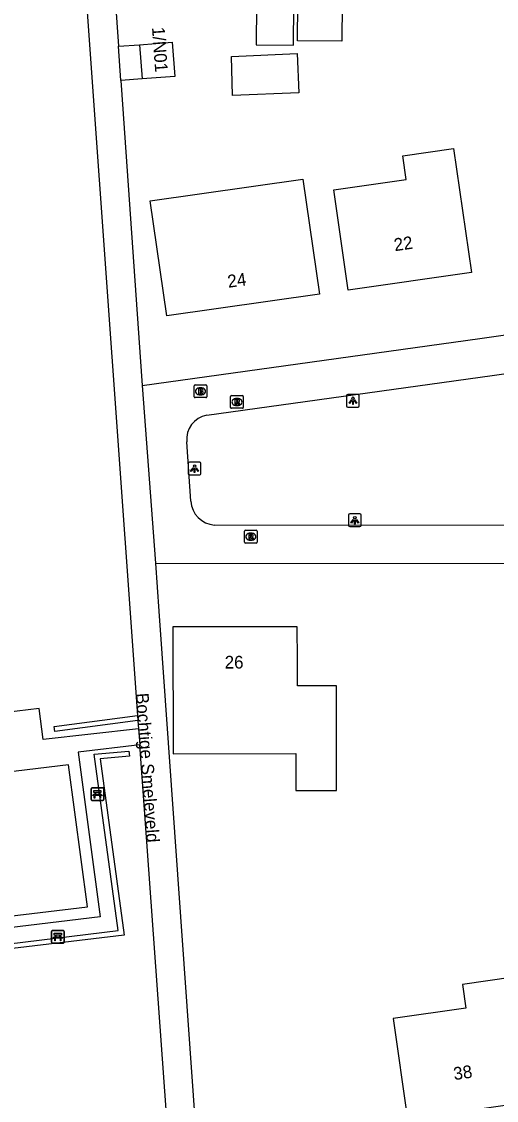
# Model space of a CAD drawing. Extents: x 162675 to 163482, y 379761 to 381227.
# Drawn here: x 162956.1 to 162993.6, y 380587.3 to 380672.3 of the extents above; entities that cross this region are included whole.
import ezdxf

# ---------------------------------------------------------------- set-up
doc = ezdxf.new("R2010")
doc.units = 0
for name, color, linetype in [('IMGEO_Bank', 7, 'Continuous'), ('IMGEO_Brandkraan', 7, 'Continuous'), ('IMGEO_Haag', 7, 'Continuous'), ('IMGEO_Lichtpunt', 7, 'Continuous'), ('IMGEO_Openbare_ruimte_label', 7, 'Continuous'), ('IMGEO_Pand', 7, 'Continuous'), ('IMGEO_Pand_nummerreeks', 7, 'Continuous'), ('IMGEO_Rijbaan_lokaal_open', 7, 'Continuous'), ('IMGEO_Rioolput', 7, 'Continuous'), ('IMGEO_Voetpad_open', 7, 'Continuous')]:
    doc.layers.add(name, color=color, linetype=linetype)

msp = doc.modelspace()

# ---------------------------------------------------------------- linework, layer by layer
at = {"layer": 'IMGEO_Bank'}
for p, q in [((162961.628, 380610.973), (162961.628, 380611.814)), ((162961.628, 380611.814), (162961.628, 380610.973)), ((162961.703, 380611.898), (162962.544, 380611.898)), ((162962.544, 380611.898), (162961.703, 380611.898)), ((162962.628, 380611.823), (162962.628, 380610.982)), ((162962.628, 380610.982), (162962.628, 380611.823)), ((162962.553, 380610.898), (162961.712, 380610.898)), ((162961.712, 380610.898), (162962.553, 380610.898)), ((162962.325, 380611.296), (162961.932, 380611.296)), ((162961.937, 380611.404), (162961.937, 380611.51)), ((162961.981, 380611.51), (162961.981, 380611.404)), ((162962.269, 380611.516), (162961.987, 380611.516)), ((162961.987, 380611.398), (162962.269, 380611.398)), ((162962.275, 380611.404), (162962.275, 380611.51)), ((162962.319, 380611.51), (162962.319, 380611.404)), ((162958.508, 380599.725), (162958.508, 380600.566)), ((162958.508, 380600.566), (162958.508, 380599.725)), ((162958.583, 380600.65), (162959.424, 380600.65)), ((162959.424, 380600.65), (162958.583, 380600.65)), ((162959.508, 380600.575), (162959.508, 380599.734)), ((162959.508, 380599.734), (162959.508, 380600.575)), ((162959.433, 380599.65), (162958.592, 380599.65)), ((162958.592, 380599.65), (162959.433, 380599.65)), ((162959.205, 380600.048), (162958.812, 380600.048)), ((162958.817, 380600.156), (162958.817, 380600.262)), ((162958.861, 380600.262), (162958.861, 380600.156)), ((162959.149, 380600.268), (162958.867, 380600.268)), ((162958.867, 380600.15), (162959.149, 380600.15)), ((162959.155, 380600.156), (162959.155, 380600.262)), ((162959.199, 380600.262), (162959.199, 380600.156))]:
    msp.add_line(p, q, dxfattribs=at)
for points in [[(162961.931, 380611.516), (162961.845, 380611.516), (162961.845, 380611.677), (162962.408, 380611.677), (162962.408, 380611.516), (162962.325, 380611.516)], [(162961.875, 380611.296), (162961.733, 380611.296), (162961.845, 380611.398), (162961.931, 380611.398)], [(162961.925, 380611.289), (162961.925, 380611.082), (162961.882, 380611.082), (162961.882, 380611.289)], [(162962.325, 380611.398), (162962.408, 380611.398), (162962.52, 380611.296), (162962.381, 380611.296)], [(162962.375, 380611.289), (162962.375, 380611.082), (162962.331, 380611.082), (162962.331, 380611.289)], [(162958.755, 380600.048), (162958.613, 380600.048), (162958.725, 380600.15), (162958.811, 380600.15)], [(162958.811, 380600.268), (162958.725, 380600.268), (162958.725, 380600.429), (162959.288, 380600.429), (162959.288, 380600.268), (162959.205, 380600.268)], [(162958.805, 380600.041), (162958.805, 380599.834), (162958.762, 380599.834), (162958.762, 380600.041)], [(162959.205, 380600.15), (162959.288, 380600.15), (162959.4, 380600.048), (162959.261, 380600.048)], [(162959.255, 380600.041), (162959.255, 380599.834), (162959.211, 380599.834), (162959.211, 380600.041)]]:
    msp.add_lwpolyline(points, dxfattribs=at)
for centre, radius, start, end in [((162961.706, 380611.82), 0.0779, 92.4484, 184.28452), ((162961.706, 380611.82), 0.0779, 92.4484, 184.28452), ((162962.55, 380611.82), 0.0779, 2.4484, 94.28452), ((162962.55, 380611.82), 0.0779, 2.4484, 94.28452), ((162961.706, 380610.976), 0.0779, 182.4484, 274.28452), ((162961.706, 380610.976), 0.0779, 182.4484, 274.28452), ((162961.875, 380611.289), 0.00671, 2.89567, 87.10433), ((162961.932, 380611.289), 0.00671, 92.89567, 177.10433), ((162961.93, 380611.509), 0.00671, 2.89567, 87.10433), ((162961.93, 380611.405), 0.00671, 272.89567, 357.10433), ((162961.987, 380611.509), 0.00671, 92.89567, 177.10433), ((162961.987, 380611.405), 0.00671, 182.89567, 267.10433), ((162962.269, 380611.509), 0.00671, 2.89567, 87.10433), ((162962.269, 380611.405), 0.00671, 272.89567, 357.10433), ((162962.326, 380611.509), 0.00671, 92.89567, 177.10433), ((162962.326, 380611.405), 0.00671, 182.89567, 267.10433), ((162962.324, 380611.289), 0.00671, 2.89567, 87.10433), ((162962.381, 380611.289), 0.00671, 92.89567, 177.10433), ((162962.55, 380610.976), 0.0779, 272.4484, 4.28452), ((162962.55, 380610.976), 0.0779, 272.4484, 4.28452), ((162958.586, 380600.572), 0.0779, 92.4484, 184.28452), ((162958.586, 380600.572), 0.0779, 92.4484, 184.28452), ((162959.43, 380600.572), 0.0779, 2.4484, 94.28452), ((162959.43, 380600.572), 0.0779, 2.4484, 94.28452), ((162958.586, 380599.728), 0.0779, 182.4484, 274.28452), ((162958.586, 380599.728), 0.0779, 182.4484, 274.28452), ((162958.755, 380600.041), 0.00671, 2.89567, 87.10433), ((162958.812, 380600.041), 0.00671, 92.89567, 177.10433), ((162958.81, 380600.261), 0.00671, 2.89567, 87.10433), ((162958.81, 380600.157), 0.00671, 272.89567, 357.10433), ((162958.867, 380600.261), 0.00671, 92.89567, 177.10433), ((162958.867, 380600.157), 0.00671, 182.89567, 267.10433), ((162959.149, 380600.261), 0.00671, 2.89567, 87.10433), ((162959.149, 380600.157), 0.00671, 272.89567, 357.10433), ((162959.206, 380600.261), 0.00671, 92.89567, 177.10433), ((162959.206, 380600.157), 0.00671, 182.89567, 267.10433), ((162959.204, 380600.041), 0.00671, 2.89567, 87.10433), ((162959.261, 380600.041), 0.00671, 92.89567, 177.10433), ((162959.43, 380599.728), 0.0779, 272.4484, 4.28452), ((162959.43, 380599.728), 0.0779, 272.4484, 4.28452)]:
    msp.add_arc(centre, radius, start, end, dxfattribs=at)
at = {"layer": 'IMGEO_Brandkraan'}
for p, q in [((162969.753, 380642.72), (162969.753, 380643.572)), ((162969.828, 380643.646), (162970.68, 380643.646)), ((162970.241, 380643.426), (162970.266, 380643.426)), ((162970.754, 380643.572), (162970.754, 380642.72)), ((162970.68, 380642.646), (162969.828, 380642.646)), ((162970.264, 380642.866), (162970.239, 380642.866))]:
    msp.add_line(p, q, dxfattribs=at)
for points in [[(162969.753, 380642.72), (162969.753, 380643.572)], [(162969.828, 380643.646), (162970.68, 380643.646)], [(162970.101, 380643.346), (162970.101, 380642.946), (162970.314, 380642.946)], [(162970.332, 380643.346), (162970.101, 380643.346)], [(162970.28, 380643.265), (162970.226, 380643.265), (162970.226, 380643.189)], [(162970.226, 380643.189), (162970.279, 380643.189)], [(162970.288, 380643.113), (162970.226, 380643.113), (162970.226, 380643.032)], [(162970.226, 380643.032), (162970.288, 380643.032)], [(162970.754, 380643.572), (162970.754, 380642.72)], [(162970.68, 380642.646), (162969.828, 380642.646)]]:
    msp.add_lwpolyline(points, dxfattribs=at)
for centre, radius, start, end in [((162969.83, 380643.57), 0.0765, 91.55205, 178.44795), ((162969.83, 380643.57), 0.0765, 91.55205, 178.44795), ((162970.281, 380643.227), 0.0379, 267.82845, 90.93552), ((162970.289, 380643.072), 0.0404, 269.87594, 90.50774), ((162970.336, 380643.201), 0.145, 59.4692, 91.53667), ((162970.361, 380643.248), 0.0922, 285.51372, 58.15012), ((162970.366, 380643.056), 0.105, 301.31148, 78.98903), ((162970.678, 380643.57), 0.0765, 1.55205, 88.44795), ((162970.678, 380643.57), 0.0765, 1.55205, 88.44795), ((162969.83, 380642.722), 0.0765, 181.55205, 268.44795), ((162969.83, 380642.722), 0.0765, 181.55205, 268.44795), ((162970.32, 380643.197), 0.251, 268.66757, 293.53466), ((162970.678, 380642.722), 0.0765, 271.55205, 358.44795), ((162970.678, 380642.722), 0.0765, 271.55205, 358.44795)]:
    msp.add_arc(centre, radius, start, end, dxfattribs=at)
for centre, major_axis, ratio, start_param, end_param in [((162970.24, 380643.146), (-0.387, 0.002), 0.722429, 4.712389, 7.853982), ((162970.265, 380643.146), (-0.39, 0.002), 0.717154, 1.570796, 4.712389)]:
    msp.add_ellipse(centre, major_axis=major_axis, ratio=ratio, start_param=start_param, end_param=end_param, dxfattribs=at)
at = {"layer": 'IMGEO_Haag'}
for points in [[(162965.305, 380617.196), (162958.775, 380616.334), (162958.723, 380616.73), (162965.276, 380617.596)], [(162948.925, 380598.844), (162963.774, 380600.633), (162961.881, 380614.533), (162964.608, 380614.784), (162964.645, 380614.386), (162962.334, 380614.173), (162964.225, 380600.285), (162949.471, 380598.507)]]:
    msp.add_lwpolyline(points, dxfattribs=at)
at = {"layer": 'IMGEO_Lichtpunt'}
for p, q in [((162981.77, 380642.801), (162981.77, 380641.994)), ((162981.77, 380642.801), (162981.77, 380641.994)), ((162982.672, 380642.896), (162981.864, 380642.896)), ((162982.672, 380642.896), (162981.864, 380642.896)), ((162982.766, 380641.994), (162982.766, 380642.801)), ((162982.766, 380641.994), (162982.766, 380642.801)), ((162981.864, 380641.9), (162982.672, 380641.9)), ((162981.864, 380641.9), (162982.672, 380641.9)), ((162969.287, 380637.457), (162969.287, 380636.65)), ((162969.287, 380637.457), (162969.287, 380636.65)), ((162970.189, 380637.552), (162969.381, 380637.552)), ((162970.189, 380637.552), (162969.381, 380637.552)), ((162970.283, 380636.65), (162970.283, 380637.457)), ((162970.283, 380636.65), (162970.283, 380637.457)), ((162969.381, 380636.556), (162970.189, 380636.556)), ((162969.381, 380636.556), (162970.189, 380636.556)), ((162981.917, 380633.384), (162981.917, 380632.577)), ((162981.917, 380633.384), (162981.917, 380632.577)), ((162982.819, 380633.479), (162982.011, 380633.479)), ((162982.819, 380633.479), (162982.011, 380633.479)), ((162982.913, 380632.577), (162982.913, 380633.384)), ((162982.913, 380632.577), (162982.913, 380633.384)), ((162982.011, 380632.483), (162982.819, 380632.483)), ((162982.011, 380632.483), (162982.819, 380632.483))]:
    msp.add_line(p, q, dxfattribs=at)
for points in [[(162982.144, 380642.465), (162982.183, 380642.437), (162981.995, 380642.175), (162981.957, 380642.202), (162982.144, 380642.465)], [(162982.246, 380642.417), (162982.293, 380642.417), (162982.293, 380642.095), (162982.246, 380642.095), (162982.246, 380642.417)], [(162982.356, 380642.437), (162982.394, 380642.464), (162982.581, 380642.202), (162982.542, 380642.174), (162982.356, 380642.437)], [(162969.661, 380637.121), (162969.7, 380637.093), (162969.512, 380636.831), (162969.474, 380636.858), (162969.661, 380637.121)], [(162969.763, 380637.073), (162969.81, 380637.073), (162969.81, 380636.751), (162969.763, 380636.751), (162969.763, 380637.073)], [(162969.873, 380637.093), (162969.911, 380637.12), (162970.098, 380636.858), (162970.059, 380636.83), (162969.873, 380637.093)], [(162982.291, 380633.048), (162982.33, 380633.02), (162982.142, 380632.758), (162982.104, 380632.785), (162982.291, 380633.048)], [(162982.393, 380633), (162982.44, 380633), (162982.44, 380632.678), (162982.393, 380632.678), (162982.393, 380633)], [(162982.503, 380633.02), (162982.541, 380633.047), (162982.728, 380632.785), (162982.689, 380632.757), (162982.503, 380633.02)]]:
    msp.add_lwpolyline(points, dxfattribs=at)
for centre in [(162982.269, 380642.599), (162969.786, 380637.255), (162982.416, 380633.182)]:
    msp.add_circle(centre, 0.0994, dxfattribs=at)
for centre, start, end in [((162981.864, 380642.801), 90, 180), ((162981.864, 380642.801), 90, 180), ((162982.672, 380642.801), 0, 90), ((162982.672, 380642.801), 0, 90), ((162981.864, 380641.994), 180, 270), ((162981.864, 380641.994), 180, 270), ((162982.672, 380641.994), 270, 0), ((162982.672, 380641.994), 270, 360), ((162969.381, 380637.457), 90, 180), ((162969.381, 380637.457), 90, 180), ((162970.189, 380637.457), 0, 90), ((162970.189, 380637.457), 0, 90), ((162969.381, 380636.65), 180, 270), ((162969.381, 380636.65), 180, 270), ((162970.189, 380636.65), 270, 0), ((162970.189, 380636.65), 270, 360), ((162982.011, 380633.384), 90, 180), ((162982.011, 380633.384), 90, 180), ((162982.819, 380633.384), 0, 90), ((162982.819, 380633.384), 0, 90), ((162982.011, 380632.577), 180, 270), ((162982.011, 380632.577), 180, 270), ((162982.819, 380632.577), 270, 0), ((162982.819, 380632.577), 270, 360)]:
    msp.add_arc(centre, 0.0946, start, end, dxfattribs=at)
at = {"layer": 'IMGEO_Pand'}
for points in [[(162981.403, 380670.751), (162977.909, 380670.776), (162977.951, 380676.747), (162981.444, 380676.723), (162981.403, 380670.751)], [(162974.644, 380670.457), (162977.58, 380670.437), (162977.602, 380673.549), (162974.666, 380673.569), (162974.644, 380670.457)], [(162965.454, 380670.466), (162968.024, 380670.653), (162968.22, 380667.959), (162965.65, 380667.772)], [(162965.454, 380670.466), (162965.65, 380667.772)], [(162977.88, 380669.767), (162978.011, 380666.67), (162972.769, 380666.448), (162972.685, 380669.548), (162977.88, 380669.767)], [(162986.465, 380659.85), (162986.198, 380661.711), (162990.197, 380662.286), (162991.607, 380652.505), (162981.89, 380651.109), (162980.753, 380659.029), (162986.465, 380659.85)], [(162979.623, 380650.808), (162967.585, 380649.089), (162966.286, 380658.154), (162978.328, 380659.874), (162979.623, 380650.808)], [(162977.884, 380621.956), (162977.874, 380624.583), (162968.072, 380624.568), (162968.088, 380614.568), (162977.768, 380614.586), (162977.761, 380611.686), (162980.961, 380611.679), (162980.981, 380619.918), (162977.884, 380619.926), (162977.884, 380621.956)], [(162986.566, 380585.786), (162996.277, 380587.155), (162994.895, 380596.958), (162990.904, 380596.396), (162991.162, 380594.513), (162985.449, 380593.707), (162986.566, 380585.786)]]:
    msp.add_lwpolyline(points, dxfattribs=at)
at = {"layer": 'IMGEO_Rijbaan_lokaal_open'}
for points in [[(162965.66, 380643.591), (162992.266, 380647.305), (163000, 380648.404), (163014.757, 380650.503), (163017.717, 380650.948)], [(162970.741, 380641.258), (162993.249, 380644.396), (163000, 380645.353), (163018.149, 380647.927)], [(162965.66, 380643.591), (162966.701, 380629.588)], [(162969.487, 380634.48), (162969.163, 380639.164)], [(163019.234, 380632.502), (163018.199, 380632.533), (163000, 380632.57), (162995.104, 380632.58), (162971.366, 380632.606)], [(162966.701, 380629.588), (162995.135, 380629.56), (163000, 380629.551), (163019.499, 380629.512)]]:
    msp.add_lwpolyline(points, dxfattribs=at)
for centre, radius, start, end in [((162971.106, 380639.342), 1.951, 100.77402, 185.22396), ((162971.488, 380634.608), 2.006, 183.6534, 266.49927)]:
    msp.add_arc(centre, radius, start, end, dxfattribs=at)
at = {"layer": 'IMGEO_Rioolput'}
for p, q in [((162972.625, 380641.878), (162972.625, 380642.73)), ((162972.7, 380642.804), (162973.552, 380642.804)), ((162973.113, 380642.584), (162973.138, 380642.584)), ((162973.626, 380642.73), (162973.626, 380641.878)), ((162973.552, 380641.804), (162972.7, 380641.804)), ((162973.136, 380642.024), (162973.111, 380642.024)), ((162973.712, 380631.262), (162973.712, 380632.114)), ((162973.787, 380632.188), (162974.639, 380632.188)), ((162974.2, 380631.968), (162974.225, 380631.968)), ((162974.713, 380632.114), (162974.713, 380631.262)), ((162974.639, 380631.188), (162973.787, 380631.188)), ((162974.223, 380631.408), (162974.198, 380631.408))]:
    msp.add_line(p, q, dxfattribs=at)
for points in [[(162972.625, 380641.878), (162972.625, 380642.73)], [(162972.7, 380642.804), (162973.552, 380642.804)], [(162973.214, 380642.502), (162972.962, 380642.504), (162972.962, 380642.104)], [(162972.962, 380642.104), (162973.086, 380642.104), (162973.086, 380642.266), (162973.097, 380642.266)], [(162973.14, 380642.423), (162973.086, 380642.423), (162973.086, 380642.342)], [(162973.086, 380642.342), (162973.138, 380642.342)], [(162973.144, 380642.237), (162973.215, 380642.104), (162973.355, 380642.104), (162973.29, 380642.23)], [(162973.626, 380642.73), (162973.626, 380641.878)], [(162973.552, 380641.804), (162972.7, 380641.804)], [(162973.712, 380631.262), (162973.712, 380632.114)], [(162973.787, 380632.188), (162974.639, 380632.188)], [(162974.713, 380632.114), (162974.713, 380631.262)], [(162974.639, 380631.188), (162973.787, 380631.188)], [(162974.301, 380631.886), (162974.049, 380631.888), (162974.049, 380631.488)], [(162974.049, 380631.488), (162974.173, 380631.488), (162974.173, 380631.65), (162974.184, 380631.65)], [(162974.227, 380631.807), (162974.173, 380631.807), (162974.173, 380631.726)], [(162974.173, 380631.726), (162974.225, 380631.726)], [(162974.231, 380631.621), (162974.302, 380631.488), (162974.442, 380631.488), (162974.377, 380631.614)]]:
    msp.add_lwpolyline(points, dxfattribs=at)
for centre, radius, start, end in [((162972.702, 380642.728), 0.0765, 91.55205, 178.44795), ((162972.702, 380642.728), 0.0765, 91.55205, 178.44795), ((162973.096, 380642.213), 0.0533, 26.02933, 88.69889), ((162973.122, 380642.531), 0.19, 274.7715, 282.96867), ((162973.146, 380642.327), 0.0964, 77.00612, 93.18647), ((162973.16, 380642.384), 0.0378, 276.66336, 79.67722), ((162973.213, 380642.392), 0.109, 350.36119, 89.41601), ((162973.211, 380642.392), 0.112, 277.58423, 350.98172), ((162973.195, 380642.177), 0.108, 29.51342, 73.79051), ((162973.55, 380642.728), 0.0765, 1.55205, 88.44795), ((162973.55, 380642.728), 0.0765, 1.55205, 88.44795), ((162972.702, 380641.88), 0.0765, 181.55205, 268.44795), ((162972.702, 380641.88), 0.0765, 181.55205, 268.44795), ((162973.55, 380641.88), 0.0765, 271.55205, 358.44795), ((162973.55, 380641.88), 0.0765, 271.55205, 358.44795), ((162973.789, 380632.112), 0.0765, 91.55205, 178.44795), ((162973.789, 380632.112), 0.0765, 91.55205, 178.44795), ((162974.637, 380632.112), 0.0765, 1.55205, 88.44795), ((162974.637, 380632.112), 0.0765, 1.55205, 88.44795), ((162973.789, 380631.264), 0.0765, 181.55205, 268.44795), ((162973.789, 380631.264), 0.0765, 181.55205, 268.44795), ((162974.183, 380631.597), 0.0533, 26.02933, 88.69889), ((162974.209, 380631.915), 0.19, 274.7715, 282.96867), ((162974.233, 380631.711), 0.0964, 77.00612, 93.18647), ((162974.247, 380631.768), 0.0378, 276.66336, 79.67722), ((162974.3, 380631.776), 0.109, 350.36119, 89.41601), ((162974.298, 380631.776), 0.112, 277.58423, 350.98172), ((162974.282, 380631.561), 0.108, 29.51342, 73.79051), ((162974.637, 380631.264), 0.0765, 271.55205, 358.44795), ((162974.637, 380631.264), 0.0765, 271.55205, 358.44795)]:
    msp.add_arc(centre, radius, start, end, dxfattribs=at)
for centre, major_axis, ratio, start_param, end_param in [((162973.112, 380642.304), (-0.387, 0.002), 0.722429, 4.712389, 7.853982), ((162973.137, 380642.304), (-0.39, 0.002), 0.717154, 1.570796, 4.712389), ((162974.199, 380631.688), (-0.387, 0.002), 0.722429, 4.712389, 7.853982), ((162974.224, 380631.688), (-0.39, 0.002), 0.717154, 1.570796, 4.712389)]:
    msp.add_ellipse(centre, major_axis=major_axis, ratio=ratio, start_param=start_param, end_param=end_param, dxfattribs=at)
at = {"layer": 'IMGEO_Voetpad_open'}
for points in [[(162962.071, 380694.445), (162962.409, 380689.802), (162962.491, 380688.633), (162963.778, 380670.344)], [(162960.008, 380688.147), (162960.246, 380688.108), (162965.276, 380617.596)], [(162963.778, 380670.344), (162965.454, 380670.466)], [(162963.967, 380667.65), (162963.778, 380670.344)], [(162965.65, 380667.772), (162963.967, 380667.65)], [(162963.967, 380667.65), (162965.66, 380643.591)], [(162966.701, 380629.588), (162966.959, 380625.81), (162969.904, 380584.293), (162970.367, 380578.072)], [(162965.351, 380616.545), (162957.849, 380615.707), (162957.527, 380618.146), (162943.646, 380616.461), (162943.88, 380614.582), (162935.364, 380613.543)], [(162965.276, 380617.596), (162965.305, 380617.196)], [(162965.305, 380617.196), (162965.351, 380616.545)], [(162965.351, 380616.545), (162965.481, 380615.267)], [(162965.481, 380615.267), (162960.611, 380614.693), (162962.344, 380601.726), (162944.492, 380599.579), (162942.987, 380612.583), (162935.972, 380611.742)], [(162972.784, 380512.688), (162969.886, 380553.083), (162969.587, 380558.14), (162965.481, 380615.267)], [(162961.331, 380602.511), (162959.837, 380613.694), (162943.984, 380611.796), (162945.282, 380600.581), (162961.331, 380602.511)]]:
    msp.add_lwpolyline(points, dxfattribs=at)

# ---------------------------------------------------------------- texts
at = {"layer": 'IMGEO_Openbare_ruimte_label'}
msp.add_text('Bochtige Smeleveld', height=1, rotation=274.1877, dxfattribs=at).set_placement((162965.154, 380619.333))
at = {"layer": 'IMGEO_Pand_nummerreeks'}
for s, rotation, p in [('1/N01', 274.17477, (162966.424, 380671.833)), ('22', 8.17467, (162985.567, 380654.184)), ('24', 7.92974, (162972.448, 380651.302)), ('26', 0.08882, (162972.155, 380621.294)), ('38', 8.02434, (162990.255, 380588.851))]:
    msp.add_text(s, height=1, rotation=rotation, dxfattribs=at).set_placement(p)

doc.saveas('drawing.dxf')
